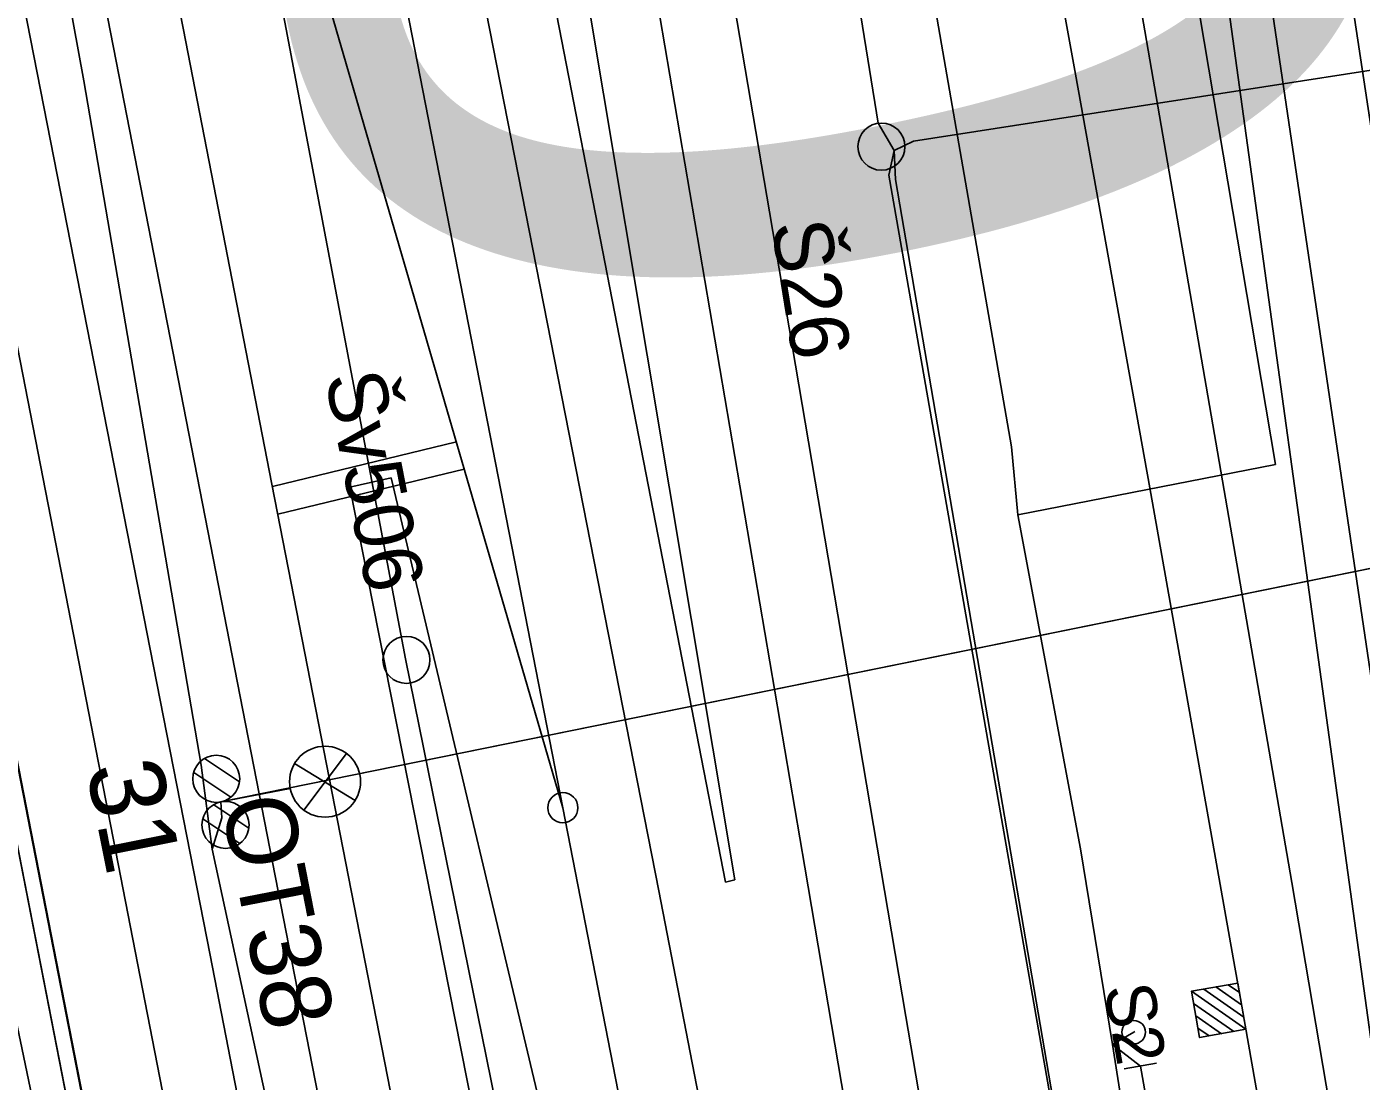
# Model space of a CAD drawing. Extents: x -545736 to -544888, y -1122892 to -1119128.
# Drawn here: x -545164.72 to -545136.37, y -1122100.45 to -1122078.04 of the extents above; entities that cross this region are included whole.
import ezdxf

# ---------------------------------------------------------------- set-up
doc = ezdxf.new("R2010")
doc.units = 0
for name, color, linetype in [('osvětlené plochy-hodnota-obrys', 7, 'Continuous'), ('Podbarveni_Nastupiste', 7, 'Continuous'), ('Podbarveni_Zastreseni_Pozemni', 7, 'Continuous'), ('Vrstva 1 - Koleje', 7, 'Continuous'), ('Vrstva 11 - Trakce', 7, 'Continuous'), ('Vrstva 14_zastreseni a nastupiste', 7, 'Continuous'), ('Vrstva 16_plochy', 7, 'Continuous'), ('Vrstva 2 - Vyhybky', 7, 'Continuous'), ('Vrstva 25', 7, 'Continuous'), ('Vrstva 26', 7, 'Continuous'), ('Vrstva 27', 7, 'Continuous'), ('Vrstva 28 - zabzar', 7, 'Continuous'), ('Vrstva 3 - Lisy - Pocitaci body', 7, 'Continuous'), ('Vrstva 35', 7, 'Continuous'), ('Vrstva 4 - Teren - stezky - prechody - plochy', 7, 'Continuous'), ('Vrstva 43', 7, 'Continuous'), ('Vrstva 44', 7, 'Continuous'), ('Vrstva 6 - Navesti', 7, 'Continuous'), ('Vrstva 7 - Namezniky-vystroj', 7, 'Continuous')]:
    doc.layers.add(name, color=color, linetype=linetype)

msp = doc.modelspace()

# ---------------------------------------------------------------- linework, layer by layer
at = {"layer": 'Podbarveni_Nastupiste'}
msp.add_lwpolyline([(-545136.516, -1122239.976), (-545138.799, -1122227.627), (-545147.465, -1122183.189), (-545157.09, -1122133.892), (-545166.638, -1122084.896), (-545171.447, -1122060.234), (-545173.829, -1122047.49), (-545174.717, -1122041.983)], dxfattribs=at)
at = {"layer": 'Podbarveni_Zastreseni_Pozemni'}
msp.add_lwpolyline([(-545138.257, -1122232.186), (-545147.796, -1122183.265), (-545157.406, -1122133.984), (-545166.925, -1122085.165), (-545175.89, -1122039.187)], dxfattribs=at)
at = {"layer": 'Vrstva 1 - Koleje'}
for points in [[(-545170.598, -1122030.894), (-545170.447, -1122031.669), (-545167.995, -1122044.234), (-545162.377, -1122063.536), (-545158.896, -1122075.51), (-545153.328, -1122094.638), (-545150.875, -1122107.224), (-545150.724, -1122107.999)], [(-545138.77, -1122062.93), (-545138.502, -1122064.693), (-545137.471, -1122071.48), (-545135.893, -1122081.93), (-545132.998, -1122100.937), (-545132.877, -1122101.728)], [(-545144.042, -1122070.186), (-545142.439, -1122079.045), (-545140.859, -1122087.836), (-545139.085, -1122097.827), (-545138.903, -1122098.857), (-545138.476, -1122101.28), (-545137.685, -1122105.765), (-545136.217, -1122114.166), (-545134.691, -1122122.995), (-545133.624, -1122129.19), (-545132.751, -1122134.262), (-545129.915, -1122150.673), (-545127.814, -1122162.832), (-545127.224, -1122166.247), (-545127.086, -1122167.045)], [(-545162.797, -1122070.887), (-545161.341, -1122078.359), (-545159.564, -1122087.471), (-545157.881, -1122096.108), (-545156.345, -1122103.98), (-545155.377, -1122108.948), (-545154.812, -1122111.848), (-545153.683, -1122117.648), (-545151.997, -1122126.296), (-545150.244, -1122135.278), (-545148.576, -1122143.835), (-545146.861, -1122152.634), (-545145.253, -1122160.881), (-545143.35, -1122170.635), (-545141.749, -1122178.861), (-545140.188, -1122186.869), (-545139.282, -1122191.516), (-545138.82, -1122193.884), (-545137.023, -1122203.118), (-545135.295, -1122211.986)], [(-545167.166, -1122073.3), (-545165.233, -1122083.213), (-545163.348, -1122092.88), (-545161.421, -1122102.785), (-545159.519, -1122112.553), (-545157.605, -1122122.374), (-545156.423, -1122128.428), (-545155.682, -1122132.235), (-545153.776, -1122142.01), (-545151.859, -1122151.863), (-545149.953, -1122161.617), (-545148.044, -1122171.433), (-545146.137, -1122181.176), (-545144.974, -1122187.135), (-545143.456, -1122194.936), (-545142.334, -1122200.685), (-545140.419, -1122210.525)], [(-545150.376, -1122073.507), (-545148.94, -1122081.972), (-545147.487, -1122090.539), (-545146.04, -1122099.073), (-545144.618, -1122107.428), (-545144.249, -1122109.575), (-545143.846, -1122111.921), (-545143.517, -1122113.832), (-545141.973, -1122122.734), (-545140.654, -1122130.261), (-545139.537, -1122136.588), (-545138.129, -1122144.487), (-545136.823, -1122151.755), (-545135.342, -1122159.915), (-545133.505, -1122169.928), (-545132.289, -1122176.511), (-545128.171, -1122198.133), (-545125.192, -1122213.779), (-545124.431, -1122217.772), (-545124.281, -1122218.558)], [(-545157.157, -1122074.99), (-545153.328, -1122094.638), (-545150.875, -1122107.224), (-545150.724, -1122107.999)]]:
    msp.add_lwpolyline(points, dxfattribs=at)
at = {"layer": 'Vrstva 11 - Trakce'}
for p, q in [((-545160.593, -1122094.514), (-545130.043, -1122088.309)), ((-545160.938, -1122093.591), (-545160.196, -1122094.086)), ((-545161.169, -1122093.887), (-545160.38, -1122094.415)), ((-545160.745, -1122094.574), (-545160.001, -1122095.071)), ((-545160.974, -1122094.872), (-545160.188, -1122095.397))]:
    msp.add_line(p, q, dxfattribs=at)
for centre in [(-545160.691, -1122094.024), (-545160.495, -1122095.004)]:
    msp.add_circle(centre, 0.5, dxfattribs=at)
at = {"layer": 'Vrstva 14_zastreseni a nastupiste'}
for points in [[(-545138.248, -1122232.184), (-545147.826, -1122183.078), (-545157.444, -1122133.764), (-545166.966, -1122084.945), (-545176.486, -1122036.133), (-545186.124, -1121986.718), (-545192.612, -1121953.456)], [(-545192.608, -1121953.452), (-545186.031, -1121987.181), (-545176.442, -1122036.358), (-545166.925, -1122085.165), (-545157.406, -1122133.984), (-545147.796, -1122183.265), (-545138.257, -1122232.186)], [(-545142.306, -1122241.006), (-545139.377, -1122240.485), (-545136.447, -1122239.964), (-545138.244, -1122230.551), (-545140.147, -1122220.747), (-545142.055, -1122210.937), (-545143.965, -1122201.145), (-545145.873, -1122191.373), (-545147.779, -1122181.574), (-545149.696, -1122171.781), (-545151.614, -1122161.976), (-545153.523, -1122152.193), (-545155.434, -1122142.369), (-545156.586, -1122136.479), (-545158.487, -1122126.724), (-545160.396, -1122116.93), (-545162.308, -1122107.103), (-545164.211, -1122097.329), (-545166.122, -1122087.54), (-545168.031, -1122077.749)], [(-545142.337, -1122240.955), (-545136.443, -1122239.964), (-545138.231, -1122230.556), (-545140.134, -1122220.752), (-545142.042, -1122210.942), (-545143.952, -1122201.15), (-545145.86, -1122191.378), (-545147.766, -1122181.579), (-545149.683, -1122171.786), (-545151.601, -1122161.981), (-545153.51, -1122152.198), (-545155.421, -1122142.374), (-545156.573, -1122136.484), (-545158.474, -1122126.729), (-545160.383, -1122116.935), (-545162.295, -1122107.108), (-545164.198, -1122097.334), (-545166.109, -1122087.545), (-545168.018, -1122077.754)]]:
    msp.add_lwpolyline(points, dxfattribs=at)
at = {"layer": 'Vrstva 16_plochy'}
msp.add_lwpolyline([(-545168.031, -1122077.749), (-545166.122, -1122087.54), (-545164.211, -1122097.329), (-545162.308, -1122107.103), (-545160.396, -1122116.93), (-545158.487, -1122126.724), (-545156.586, -1122136.479), (-545155.434, -1122142.369), (-545153.523, -1122152.193), (-545151.614, -1122161.976), (-545149.696, -1122171.781), (-545147.779, -1122181.574), (-545145.873, -1122191.373), (-545143.965, -1122201.145), (-545142.055, -1122210.937)], dxfattribs=at)
at = {"layer": 'Vrstva 2 - Vyhybky'}
for points in [[(-545157.157, -1122074.99), (-545153.328, -1122094.638), (-545150.875, -1122107.224), (-545150.724, -1122107.999)], [(-545158.896, -1122075.51), (-545153.328, -1122094.638)]]:
    msp.add_lwpolyline(points, dxfattribs=at)
msp.add_circle((-545153.328, -1122094.638), 0.32, dxfattribs=at)
at = {"layer": 'Vrstva 25'}
for p, q in [((-545157.921, -1122093.488), (-545158.834, -1122094.687)), ((-545157.742, -1122094.487), (-545159.026, -1122093.695)), ((-545159.121, -1122094.227), (-545160.593, -1122094.514))]:
    msp.add_line(p, q, dxfattribs=at)
msp.add_lwpolyline([(-545160.593, -1122094.514), (-545130.043, -1122088.309)], dxfattribs=at)
msp.add_circle((-545158.38, -1122094.085), 0.754, dxfattribs=at)
at = {"layer": 'Vrstva 26'}
for points in [[(-545160.775, -1122095.518), (-545161.014, -1122093.734), (-545163.502, -1122079.184), (-545167.551, -1122057.091), (-545168.392, -1122052.538), (-545169.161, -1122050.878), (-545169.174, -1122050.278), (-545169.366, -1122049.522)], [(-545151.629, -1122142.608), (-545152.385, -1122137.018), (-545157.665, -1122109.959), (-545160.775, -1122095.518), (-545160.575, -1122094.854), (-545160.593, -1122094.514)]]:
    msp.add_lwpolyline(points, dxfattribs=at)
at = {"layer": 'Vrstva 27'}
msp.add_line((-545141.22, -1122099.426), (-545141.18, -1122099.394), dxfattribs=at)
msp.add_circle((-545141.2, -1122099.41), 0.25, dxfattribs=at)
at = {"layer": 'Vrstva 28 - zabzar'}
for points in [[(-545138.67, -1122118.4), (-545141.31, -1122101.84), (-545141.65, -1122099.67), (-545142.33, -1122095.51), (-545143.66, -1122088.41), (-545143.8, -1122086.97), (-545147.38, -1122066.33), (-545147.52, -1122065.15), (-545152.25, -1122042.18), (-545153.51, -1122034.19), (-545154.39, -1122028.58), (-545155.3, -1122025.92), (-545157.6, -1122013.1), (-545161.86, -1121989.41), (-545162.1, -1121988.9)], [(-545143.66, -1122088.41), (-545138.19, -1122087.34), (-545140.11, -1122075.95), (-545141.08, -1122065.07), (-545141.12, -1122062.91), (-545140.43, -1122062.88), (-545140.7, -1122062.15)], [(-545141.2, -1122099.41), (-545141.65, -1122099.67), (-545141.06, -1122100.13)]]:
    msp.add_lwpolyline(points, dxfattribs=at)
at = {"layer": 'Vrstva 3 - Lisy - Pocitaci body'}
for p, q in [((-545139.192, -1122098.4), (-545138.955, -1122098.566)), ((-545139.975, -1122098.539), (-545138.816, -1122099.349)), ((-545139.714, -1122098.493), (-545138.862, -1122099.088)), ((-545139.453, -1122098.447), (-545138.908, -1122098.827)), ((-545139.929, -1122098.8), (-545139.077, -1122099.396)), ((-545139.882, -1122099.062), (-545139.338, -1122099.442)), ((-545139.836, -1122099.322), (-545139.599, -1122099.488))]:
    msp.add_line(p, q, dxfattribs=at)
msp.add_lwpolyline([(-545138.99, -1122098.365), (-545138.816, -1122099.349), (-545139.8, -1122099.524), (-545139.975, -1122098.539)], close=True, dxfattribs=at)
at = {"layer": 'Vrstva 35'}
msp.add_line((-545143.66, -1122088.41), (-545138.19, -1122087.34), dxfattribs=at)
at = {"layer": 'Vrstva 4 - Teren - stezky - prechody - plochy'}
for points in [[(-545133.405, -1122116.375), (-545134.411, -1122116.469), (-545137.844, -1122096.227), (-545141.752, -1122073.558), (-545147.149, -1122044.385), (-545150.888, -1122024.642), (-545146.335, -1122023.86)], [(-545133.405, -1122116.375), (-545134.922, -1122101.254), (-545135.901, -1122093.602), (-545138.886, -1122073.467), (-545143.407, -1122043.778), (-545146.335, -1122023.86)], [(-545137.774, -1122154.868), (-545140, -1122143.509), (-545142.031, -1122132.009), (-545144.423, -1122118.141), (-545148.187, -1122095.9), (-545152.964, -1122067.836), (-545157.177, -1122042.834), (-545160.057, -1122026.36), (-545161.613, -1122026.681)], [(-545149.873, -1122096.222), (-545149.677, -1122096.168), (-545154.325, -1122068.305), (-545157.577, -1122049.178), (-545161.613, -1122026.681)], [(-545149.873, -1122096.222), (-545155.607, -1122066.724), (-545159.126, -1122048.447), (-545159.32, -1122047.1), (-545163.333, -1122026.973), (-545164.703, -1122027.28)], [(-545137.774, -1122154.868), (-545138.748, -1122154.961), (-545141.445, -1122143.846), (-545144.077, -1122132.149), (-545146.793, -1122119.618), (-545151.286, -1122096.405), (-545157.101, -1122066.77), (-545160.819, -1122047.322), (-545164.703, -1122027.28)], [(-545130.366, -1122251.034), (-545131.253, -1122251.107), (-545132.894, -1122241.41), (-545134.482, -1122233.166), (-545143.993, -1122184.403), (-545152.068, -1122142.857), (-545160.819, -1122097.773), (-545168.806, -1122057.035), (-545170.526, -1122047.801), (-545171.946, -1122039.29), (-545172.394, -1122035.194), (-545171.448, -1122035.061)], [(-545130.366, -1122251.034), (-545131.796, -1122240.905), (-545132.966, -1122233.188), (-545134.639, -1122223.584), (-545142.301, -1122184.068), (-545150.498, -1122141.846), (-545159.147, -1122097.573), (-545167.246, -1122056.111), (-545171.448, -1122035.061)], [(-545168.018, -1122077.754), (-545166.109, -1122087.545), (-545164.198, -1122097.334), (-545162.295, -1122107.108), (-545160.383, -1122116.935), (-545158.474, -1122126.729), (-545156.573, -1122136.484), (-545155.421, -1122142.374), (-545153.51, -1122152.198), (-545151.601, -1122161.981), (-545149.683, -1122171.786), (-545147.766, -1122181.579), (-545145.86, -1122191.378), (-545143.952, -1122201.15), (-545142.042, -1122210.942)], [(-545151.762, -1122118.914), (-545154.866, -1122102.946), (-545157.854, -1122087.822), (-545156.978, -1122087.626)], [(-545151.762, -1122118.914), (-545150.234, -1122118.609), (-545152.201, -1122108.07), (-545153.275, -1122103.226), (-545156.978, -1122087.626)]]:
    msp.add_lwpolyline(points, dxfattribs=at)
at = {"layer": 'Vrstva 43'}
for centre in [(-545146.561, -1122080.585), (-545156.651, -1122091.495)]:
    msp.add_circle(centre, 0.5, dxfattribs=at)
at = {"layer": 'Vrstva 44'}
for points in [[(-545135.113, -1122107.162), (-545140.717, -1122066.523), (-545146.986, -1122027.871), (-545147.057, -1122027.496)], [(-545154.934, -1122028.908), (-545154.851, -1122029.14), (-545146.628, -1122080.085), (-545146.29, -1122080.665)], [(-545156.673, -1122091.474), (-545168.002, -1122031.679), (-545168.03, -1122031.491)], [(-545143.319, -1122213.395), (-545144.843, -1122204.729), (-545148.45, -1122187.063), (-545149.937, -1122179.183), (-545149.989, -1122178.935), (-545150.06, -1122178.615), (-545151.471, -1122170.999), (-545155.095, -1122153.22), (-545158.425, -1122136.668), (-545159.656, -1122130.551), (-545159.747, -1122130.264), (-545159.786, -1122129.987), (-545161.259, -1122119.445), (-545164.501, -1122101.273), (-545167.835, -1122085.304), (-545168.587, -1122082.897), (-545168.661, -1122082.704), (-545168.732, -1122082.46), (-545171.358, -1122068.69)], [(-545100.749, -1122302.024), (-545108.572, -1122258.755), (-545108.679, -1122258.214), (-545108.742, -1122257.838), (-545117.129, -1122210.278), (-545117.262, -1122209.864), (-545117.23, -1122209.512), (-545121.572, -1122184.377), (-545121.632, -1122183.916), (-545121.724, -1122183.534), (-545124.194, -1122170.238), (-545124.353, -1122170.102), (-545124.575, -1122169.952), (-545130.38, -1122170.732), (-545130.684, -1122170.66), (-545130.921, -1122170.43), (-545138.173, -1122128.601), (-545138.227, -1122128.313), (-545138.283, -1122127.929), (-545146.258, -1122081.287), (-545146.29, -1122080.665), (-545145.881, -1122080.467), (-545110.994, -1122075.048)], [(-545130.684, -1122170.66), (-545130.826, -1122170.269), (-545131.166, -1122166.742), (-545138.112, -1122128.477), (-545138.283, -1122127.929), (-545138.337, -1122127.277), (-545146.405, -1122081.19), (-545146.29, -1122080.665)], [(-545156.673, -1122091.474), (-545148.447, -1122131.998), (-545140.703, -1122172.502), (-545140.602, -1122172.723)]]:
    msp.add_lwpolyline(points, dxfattribs=at)
at = {"layer": 'Vrstva 6 - Navesti'}
for p, q in [((-545140.715, -1122100.069), (-545141.405, -1122100.191)), ((-545140.818, -1122101.495), (-545141.06, -1122100.13))]:
    msp.add_line(p, q, dxfattribs=at)
at = {"layer": 'Vrstva 7 - Namezniky-vystroj'}
for p, q in [((-545159.498, -1122087.809), (-545155.591, -1122086.862)), ((-545159.383, -1122088.399), (-545155.424, -1122087.439))]:
    msp.add_line(p, q, dxfattribs=at)

# ---------------------------------------------------------------- texts
at = {"layer": 'osvětlené plochy-hodnota-obrys'}
msp.add_text('30', height=22.7812, rotation=281.0956, dxfattribs=at).set_placement((-545163.755, -1122052.96))
at = {"layer": 'Vrstva 11 - Trakce'}
msp.add_text('31', height=1.6, rotation=281.2724, dxfattribs=at).set_placement((-545163.461, -1122093.785))
at = {"layer": 'Vrstva 25'}
msp.add_text('OT38', height=1.5, rotation=281.0264, dxfattribs=at).set_placement((-545160.593, -1122094.514))
at = {"layer": 'Vrstva 43'}
for s, rotation, p in [('Š26', 279.169, (-545148.904, -1122082.237)), ('Šv506', 281.0323, (-545158.386, -1122085.473))]:
    msp.add_text(s, height=1.25, rotation=rotation, dxfattribs=at).set_placement(p)
at = {"layer": 'Vrstva 6 - Navesti'}
msp.add_text('S2', height=1.05, rotation=279.9333, dxfattribs=at).set_placement((-545141.834, -1122098.462))

doc.saveas('drawing.dxf')
